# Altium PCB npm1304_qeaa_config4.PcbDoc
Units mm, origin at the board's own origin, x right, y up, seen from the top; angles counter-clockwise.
Board outline 16.8 x 14 mm, 4 copper layers (Top Layer, Mid-Layer 1, Mid-Layer 2, Bottom Layer), stack 1.592 mm thick; 25 components, 32 nets, 81 pads, 59 vias.
Unrouted connection lines stored in the file: 23.
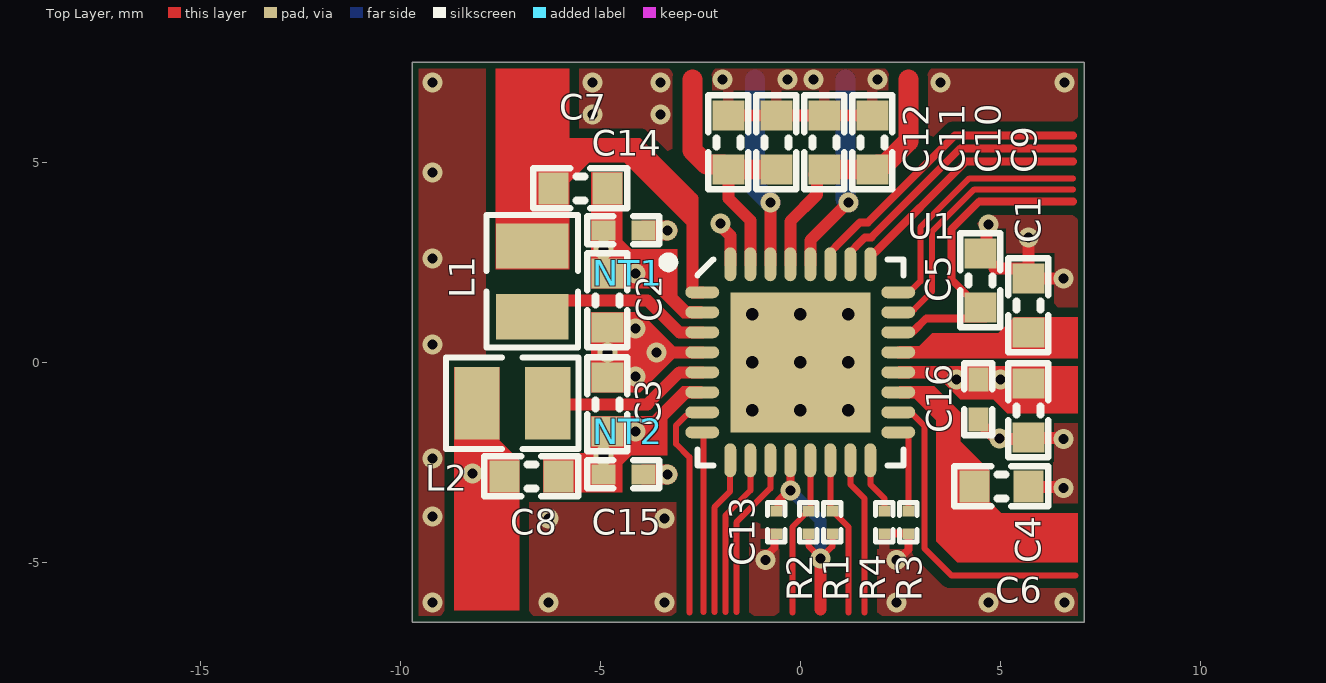
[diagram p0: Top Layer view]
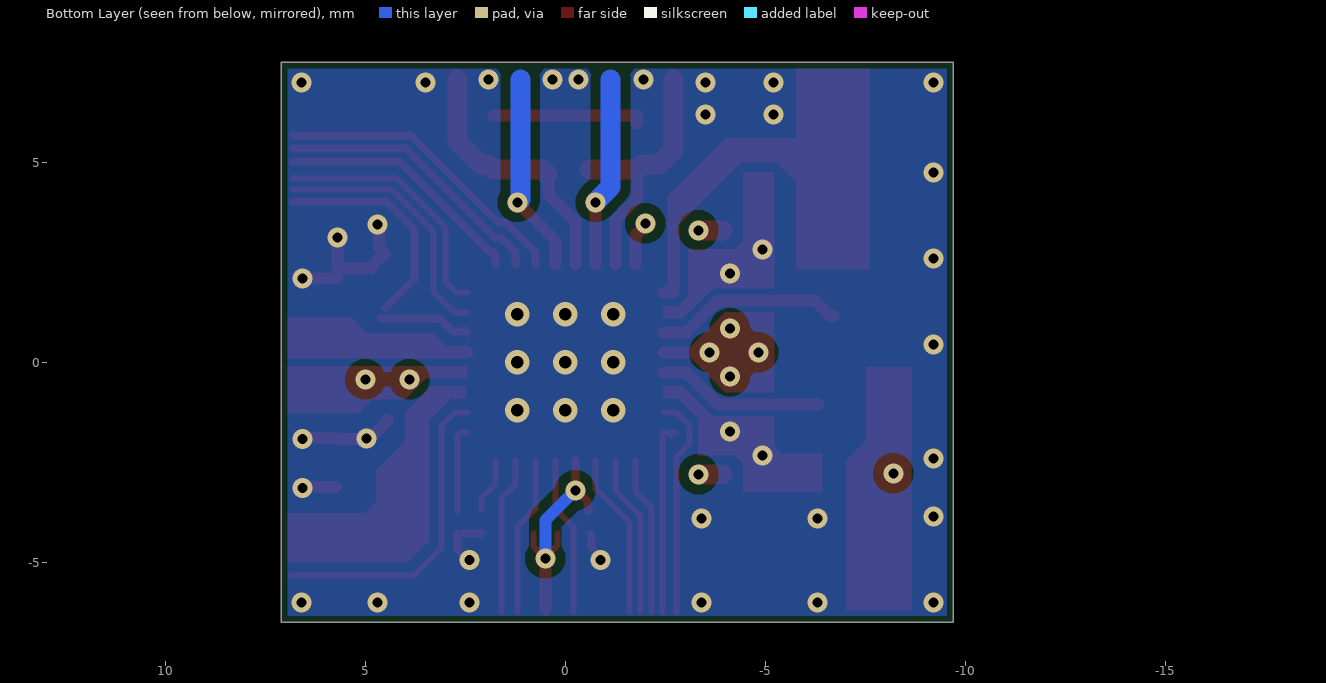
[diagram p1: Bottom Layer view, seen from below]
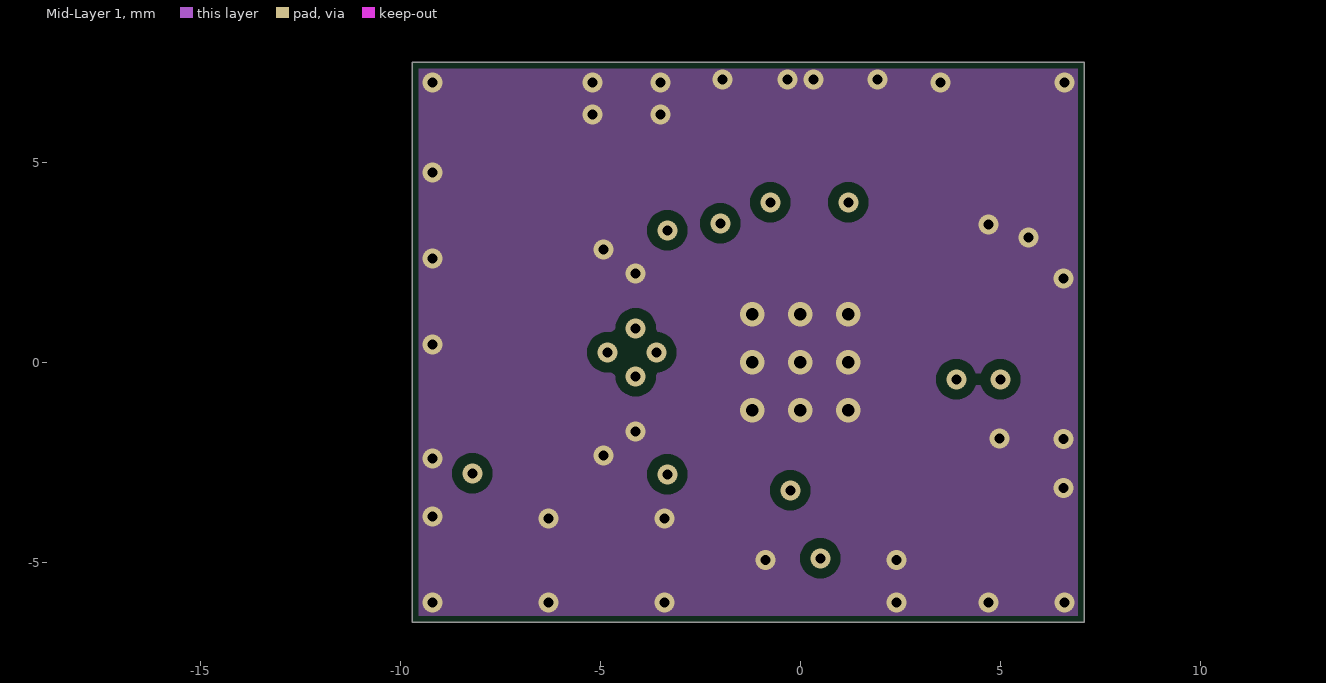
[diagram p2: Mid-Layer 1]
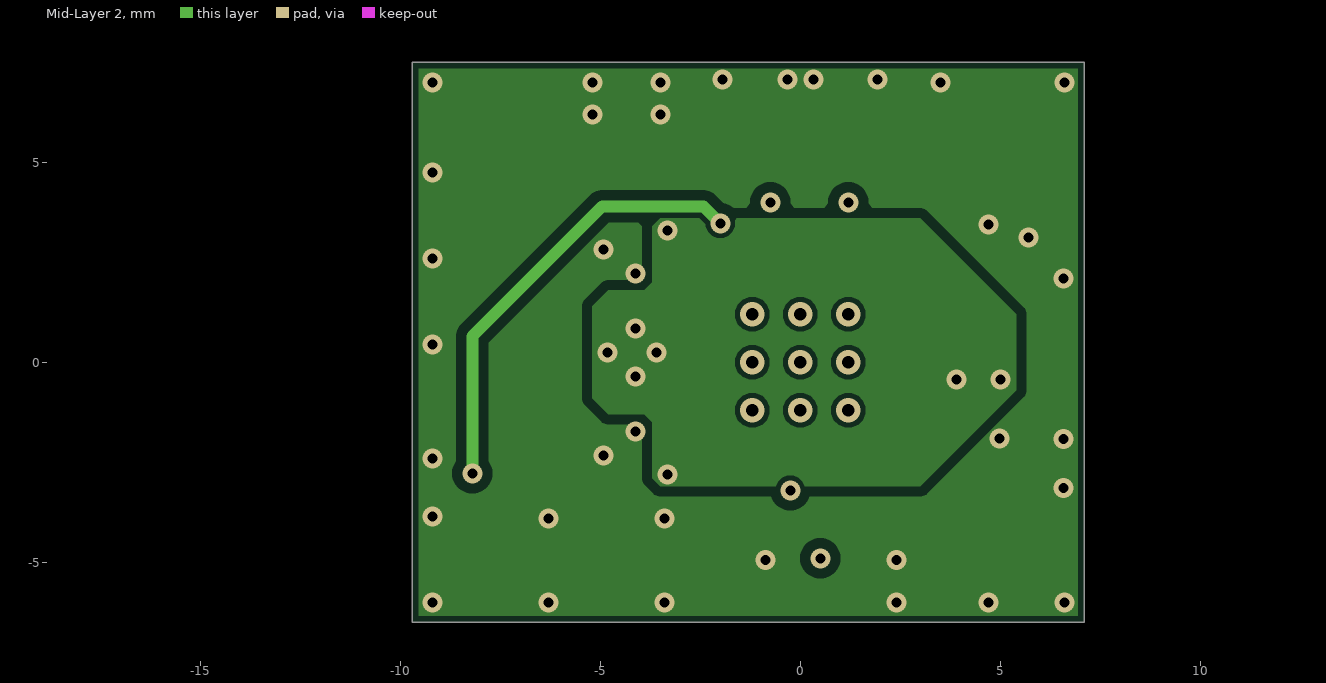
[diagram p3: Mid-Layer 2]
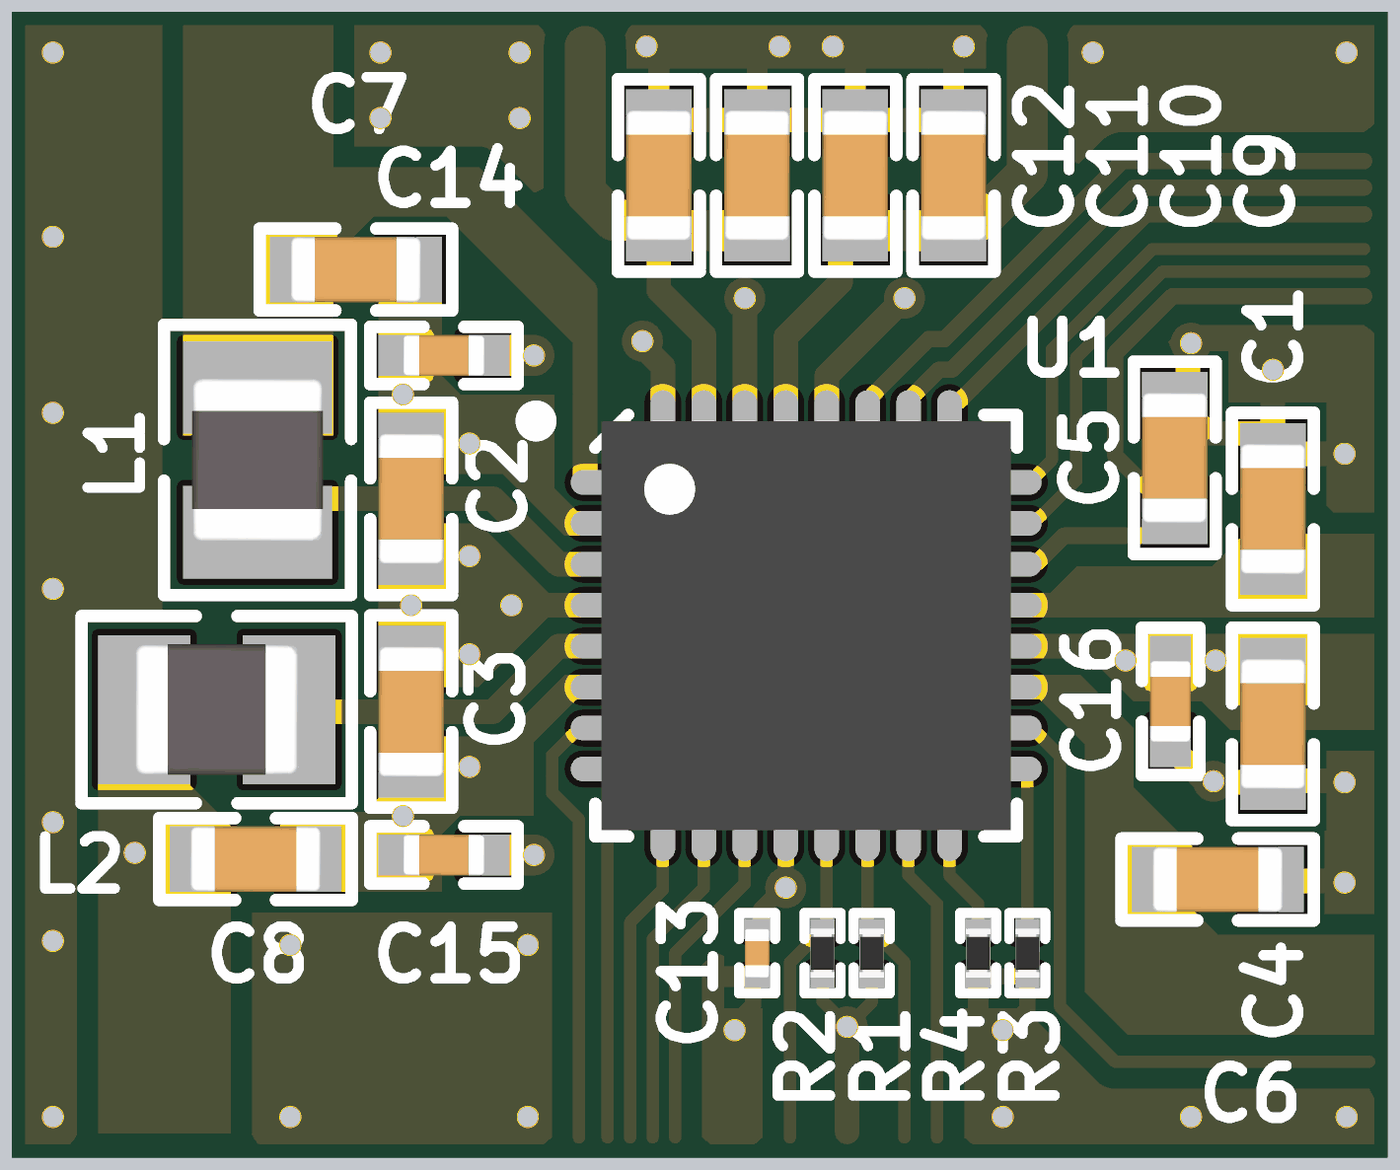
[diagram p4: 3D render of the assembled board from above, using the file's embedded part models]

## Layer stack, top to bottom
Top Solder: solder mask 0.0102, Solder Resist, Dk 3.5
Top Layer: signal copper 0.0356
Dielectric1: prepreg 0.075, FR-4, Dk 4.8
Mid-Layer 1: signal copper 0.0356
Dielectric2: core 1.3, FR-4, Dk 4.8
Mid-Layer 2: signal copper 0.0356
Dielectric 2: prepreg 0.075, FR-4, Dk 4.8
Bottom Layer: signal copper 0.0356
Bottom Solder: solder mask 0.0102, Solder Resist, Dk 3.5

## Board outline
-9.7,-6.5 -9.7,7.5 7.1,7.5 7.1,-6.5

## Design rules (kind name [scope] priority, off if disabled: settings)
BoardOutlineClearance [All] p1: gap=0.15 ignorepadtopadclearanceinfootprint=FALSE
Clearance Clearance_PVSS_Via [InNet('PVSS1') or InNet('PVSS2') vs InNet('GND')] p1: gap=0.125 ignorepadtopadclearanceinfootprint=FALSE except(0.025: SMDPad-Via) // PVSS1 and PVSS2 GND-via clearance
Clearance Polygon_Clearance [(InNamedPolygon('Top_Layer-GND')) or (InNamedPolygon('Bottom_Layer-GND')) or (InNamedPolygon('Mid_Layer_1-GND')) or (InNamedPolygon('Mid_Layer_2-GND'))] p2: gap=0.254 ignorepadtopadclearanceinfootprint=FALSE except(0: Arc-Hole Track-Hole SMDPad-Hole THPad-Hole Via-Hole Fill-Hole Poly-Hole Region-Hole Text-Hole)
Clearance [All] p3: gap=0.125 ignorepadtopadclearanceinfootprint=FALSE
ComponentClearance [All] p1 off: gap=0.254 collisioncheckmode=3 verticalgap=0.254 showdistances=FALSE
DiffPairsRouting [All] p1: maxlimit=0.15 minlimit=0.127 mostfreqgap=0.15 toplayer_mingap=0.15 toplayer_minwidth=0.15 toplayer_maxwidth=0.15 toplayer_prefwidth=0.15 bottomlayer_mingap=0.15 bottomlayer_minwidth=0.15 bottomlayer_maxwidth=0.15 bottomlayer_prefwidth=0.15 impedanceprofiledriven=TRUE impedanceprofileid={DBD80B30-E3CF-4860-A6C7-45E32F93C55D} impedanceprofilevalue=90.000000 maxuncoupledlength=12.7
FabricationTestPointUsage TestPointUsage [All] p1: valid=0 allowmultiple=FALSE
FabricationTestpoint Testpoint [All] p1: side=3 testpointundercomponent=TRUE minsize=1.016 maxsize=2.54 preferedsize=1.524 minholesize=0 maxholesize=1.016 preferedholesize=0.813 testpointgrid=0.025 allowsidetop=TRUE allowsidebottom=TRUE usegrid=TRUE gridtolerance=0
Height [All] p1 off: minheight=0 maxheight=25.4 prefheight=12.7
HoleSize [All] p1: absolutevalues=TRUE maxlimit=5 minlimit=0.1 maxpercent=80.000 minpercent=20.000
MinimumAnnularRing [All] p1 off: minimumring=0.75
PolygonConnect PolygonConnect_GND [InNet('GND')] p1: thpad.connectstyle=Relief thpad.reliefconductorwidth=0.254 thpad.reliefentries=4 thpad.polygonreliefangle="90 Angle" thpad.airgapwidth=0.254 smdpad.connectstyle=Relief smdpad.reliefconductorwidth=0.254 smdpad.reliefentries=4 smdpad.polygonreliefangle="90 Angle" smdpad.airgapwidth=0.254 via.connectstyle=Direct via.reliefconductorwidth=0.254 via.reliefentries=4 via.polygonreliefangle="90 Angle" via.airgapwidth=0.254
PolygonConnect [All] p2: connectstyle=Direct reliefconductorwidth=0.254 reliefentries=4 polygonreliefangle="90 Angle" airgapwidth=0.254
RoutingVias [All] p1: holewidth=0.305 width=0.61 viastyle="Through Hole" minholewidth=0.305 minwidth=0.61 maxholewidth=0.711 maxwidth=1.27 useviatemplates=TRUE viatemplateguid#1={6F225C6A-EE86-4657-A426-C9A0349870D4} viatemplatename#1=v50h25m0mx0
ShortCircuit ShortCircuit_PVSS [InNet('PVSS1') or InNet('PVSS2') vs InNet('GND')] p1: allowed=TRUE
ShortCircuit [All] p2: allowed=FALSE
SilkToSolderMaskClearance SilkscreenOverComponentPads [IsPad] p1: minsilkscreentomaskgap=0.254 clearancetoexposedcopper=TRUE
SolderMaskExpansion SolderMaskExpansion_Vias [IsVia] p1: expansion=0.102 istentingtop=TRUE
SolderMaskExpansion [All] p2: expansion=0.076 istentingtop=FALSE
SupplyNets "Schematic Supply Nets_13" [InNet('PVSS2')] p1: voltage=0.000
SupplyNets "Schematic Supply Nets_12" [InNet('VBUSOUT')] p2: voltage=0.000
SupplyNets "Schematic Supply Nets_11" [InNet('VINLDO2')] p3: voltage=0.000
SupplyNets "Schematic Supply Nets_10" [InNet('VBAT')] p4: voltage=0.000
SupplyNets "Schematic Supply Nets_9" [InNet('VOUTLDO1')] p5: voltage=0.000
SupplyNets "Schematic Supply Nets_8" [InNet('VOUTLDO2')] p6: voltage=0.000
SupplyNets "Schematic Supply Nets_7" [InNet('VDDIO')] p7: voltage=0.000
SupplyNets "Schematic Supply Nets_6" [InNet('GND')] p8: voltage=0.000
SupplyNets "Schematic Supply Nets_5" [InNet('VINLDO1')] p9: voltage=0.000
SupplyNets "Schematic Supply Nets_4" [InNet('VSYS')] p10: voltage=0.000
SupplyNets "Schematic Supply Nets_3" [InNet('VBUSIN')] p11: voltage=0.000
SupplyNets "Schematic Supply Nets_2" [InNet('PVSS1')] p12: voltage=0.000
SupplyNets "Schematic Supply Nets_1" [InNet('VOUT2')] p13: voltage=0.000
SupplyNets "Schematic Supply Nets" [InNet('VOUT1')] p14: voltage=0.000
UnRoutedNet [All] p1: checkbadconnections=TRUE
Width [All] p1: maxlimit=2 minlimit=0.12 preferedwidth=0.3
21 further rules are at their usual default settings.

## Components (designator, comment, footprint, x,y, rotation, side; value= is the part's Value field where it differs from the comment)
C1 "1.0µF" CAPC1608X06L 5.7,1.425 r270 top
C2 "10µF" CAPC1608X06L -4.825,1.55 r270 top
C3 "10µF" CAPC1608X06L -4.825,-1.05 r90 top
C4 "10µF" CAPC1608X06L 5.7,-1.2 r90 top
C5 "1.0µF" CAPC1608X06L 4.5,2.05 r270 top
C6 "2.2µF" CAPC1608X06L 5.025,-3.1 r180 top
C7 "10µF" CAPC1608X06L -5.5,4.35 r180 top
C8 "10µF" CAPC1608X06L -6.725,-2.85 r180 top
C9 "10µF" CAPC1608X06L 1.8,5.5 r270 top
C10 "10µF" CAPC1608X06L 0.6,5.5 r270 top
C11 "10µF" CAPC1608X06L -0.6,5.5 r270 top
C12 "10µF" CAPC1608X06L -1.8,5.5 r270 top
C13 "100nF" CAPC0603X03L_C -0.6,-4 r270 top
C14 "100nF" CAPC1005X04L -4.425,3.3 r180 top
C15 "100nF" CAPC1005X04L -4.425,-2.8 r180 top
C16 "100nF" CAPC1005X04L 4.45,-0.925 r270 top
L1 "2.2µH" INDC2016X10N -6.7,2.025 r270 top
L2 "2.2µH" INDC2016X10N -7.2,-1.025 r0 top
NT1 "Net tie" "2 PIN STARPOINT" -4.317,2.225 r0 top net-tie
NT2 "Net tie" "2 PIN STARPOINT" -4.317,-1.725 r0 top net-tie
R1 "10k" RESC0603X03L_C 0.8,-4 r270 top
R2 "10k" RESC0603X03L_C 0.2,-4 r270 top
R3 "47k" RESC0603X03L_C 2.7,-4 r270 top
R4 "150k" RESC0603X03L_C 2.1,-4 r270 top
U1 "nPM1304-QEAA" Nordic_QFN50P500X500X90-33N 0,0 r0 top locked

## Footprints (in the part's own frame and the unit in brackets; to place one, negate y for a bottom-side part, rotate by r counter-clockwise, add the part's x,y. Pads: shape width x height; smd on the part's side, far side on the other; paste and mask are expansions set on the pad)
"2 PIN STARPOINT" [mil]
  round 6 smd paste-196.85 mask-196.85: 1(8,0) 2(-8,0)
  Top Layer region: -8,-3 8,-3 8,3 -8,3
CAPC0603X03L_C [mm] "Chip Capacitor, 2-Leads, Body 0.6x0.3mm, IPC High Density"
  rect 0.27x0.3 smd mask+0.05: 1(-0.285,0) 2(0.285,0)
  silkscreen extent -0.49,-0.22 0.49,0.22, body extent -0.3,-0.15 0.3,0.15, height 0.3
CAPC1005X04L [mm] "Chip Capacitor, 2-Leads, Body 1.0x0.5mm, IPC High Density"
  rect 0.6x0.5 smd: 1(-0.5,0) 2(0.5,0)
  silkscreen extent -0.9,-0.35 0.9,0.35, body extent -0.5,-0.25 0.5,0.25, height 0.5
CAPC1608X06L [mm] "Chip Capacitor, 2-Leads, Body 1.6x0.8mm, IPC High Density"
  rect 0.75x0.8 smd: 1(-0.675,0) 2(0.675,0)
  silkscreen extent -1.17,-0.5 1.17,0.5, body extent -0.8,-0.4 0.8,0.4, height 0.8
INDC2016X10N [mm] "Chip Inductor, 2-Leads, Body 2.00x1.60mm, IPC Medium Density"
  rect 1.13x1.82 smd: 1(-0.885,0) 2(0.885,0)
  silkscreen extent -1.65,-1.14 1.65,1.14, body extent -1,-0.8 1,0.8, height 1
Nordic_QFN50P500X500X90-33N [mm] "QFN32 5x5x0.85mm, 0.5mm pitch - Medium Density"
  oval 0.85x0.3 smd mask+0.076: 1(-2.45,1.75) 2(-2.45,1.25) 3(-2.45,0.75) 4(-2.45,0.25) 5(-2.45,-0.25) 6(-2.45,-0.75) 7(-2.45,-1.25) 8(-2.45,-1.75) 17(2.45,-1.75) 18(2.45,-1.25) 19(2.45,-0.75) 20(2.45,-0.25) 21(2.45,0.25) 22(2.45,0.75) 23(2.45,1.25) 24(2.45,1.75)
  oval 0.3x0.85 smd mask+0.076: 9(-1.75,-2.45) 10(-1.25,-2.45) 11(-0.75,-2.45) 12(-0.25,-2.45) 13(0.25,-2.45) 14(0.75,-2.45) 15(1.25,-2.45) 16(1.75,-2.45) 25(1.75,2.45) 26(1.25,2.45) 27(0.75,2.45) 28(0.25,2.45) 29(-0.25,2.45) 30(-0.75,2.45) 31(-1.25,2.45) 32(-1.75,2.45)
  rect 3.5x3.5 smd: 33(0,0)
  silkscreen extent -3.42,-2.57 2.57,2.62, body extent -2.5,-2.5 2.5,2.5, height 0.9
RESC0603X03L_C [mm] "Chip Resistor, 2-Leads, Body 0.6x0.3mm, IPC High Density"
  rect 0.27x0.3 smd: 1(-0.285,0) 2(0.285,0)
  silkscreen extent -0.49,-0.22 0.49,0.22, body extent -0.3,-0.15 0.3,0.15, height 0.23

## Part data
C1: library part C0603-1µ0-25V-X5R, "Capacitor, X5R, ±10%, 25V", Manufacturer=N.A., Part number NEMS=100200687
C2 C3 C4 C7 C8 C9 C10 C11 C12: library part C0603-10µ, "Capacitor, X5R, ±20%", Manufacturer=N.A., Part number IPS=00000007785, Part number NEMS=100200275
C5: library part C0603-1µ0-10V-X5R, "Capacitor, Ceramic, 1.0µF 10V X5R 0603,±10%", Manufacturer=N.A., Part number NEMS=100200528
C6: library part C0603-2.2µ-16V-X7R, "Capacitor, Ceramic, X7R, ±10%, 16V", Manufacturer="Taiyo Yuden", Manufacturer Part Number=EMK107BB7225KA-T, Part number IPS=N.A., Part number NEMS=100200439, Supplier Part Number 1=587-5835-2-ND
C13: library part C0201-100n, "Capacitor, X5R, ±10%, 100nF, 16V", Manufacturer=N.A., Part number IPS="00000001248, 00000002505", Part number NEMS=100200078, Part number Norautron=262071862
C14 C15 C16: library part C0402-100n-16V-X7R-C0402C104M4RAC7867, "Capacitor, Ceramic, X7R, ±20%, 16V", Manufacturer=Kemet, Manufacturer Part Number=C0402C104M4RAC7867, Part number IPS=N.A., Part number NEMS=100200504, Supplier Part Number 1=399-C0402C104M4RAC7867CT-ND
L1 L2: library part L0806-2µ2-2500mA-73mOhm-CIGT201610EH2R2MNE, "Inductor, Irms=2.5A, Isat=2.9A, ±20%, DCR=73mΩ", Manufacturer="Samsung Electro-Mechanics America", Manufacturer Part Number=CIGT201610EH2R2MNE, Part number IPS=N.A., Part number NEMS=100300400, Part number Norautron=26521789, Supplier Part Number 1=1276-6901-1-ND
NT1 NT2: library part "2 pin starpoint", "Starpoint", Manufacturer=N.A., Part number NEMS=100500603
R1 R2: library part R0201-10k, "Resistor, ±1%, 0.05W", Manufacturer=N.A., Part number IPS=00000001255, Part number NEMS=100100065, Part number Norautron=26107101
R3: library part R0201-47k, "Resistor, ±1%, 0.05W", Manufacturer=N.A., Part number IPS=00000001423, Part number NEMS=100100076
R4: library part R0201-150k, "Resistor, ±1%, 0.05W", Manufacturer=N.A., Part number IPS=00000001422, Part number NEMS=100100082
U1: "Li-Ion/Li-Polymer USB-C battery charger with high efficiency buck regulators, LDOs or load switches, LED drivers, TWI and VBUSOUT", Manufacturer="Nordic Semiconductor", Part number IPS=N.A., Part number NEMS=102000396

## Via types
v1: diameter 0.5, hole 0.25, Top Layer to Bottom Layer, tented both sides, 50 vias
v2: diameter 0.61, hole 0.305, Top Layer to Bottom Layer, tented both sides, 9 vias

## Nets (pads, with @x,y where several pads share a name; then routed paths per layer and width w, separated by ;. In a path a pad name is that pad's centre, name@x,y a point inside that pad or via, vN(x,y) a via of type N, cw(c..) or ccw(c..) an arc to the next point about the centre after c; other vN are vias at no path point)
CC1: U1.23 | length 6.5
  Top Layer w0.15: U1.23 2.766,1.25 2.841,1.325 2.851,1.325 3.299,1.772 3.299,3.273 4.351,4.325 6.813,4.325
CC2: U1.24 | length 6.3
  Top Layer w0.15: U1.24 2.725,1.75 3,2.025 3,3.375 4.225,4.6 6.813,4.6
GND: C1.1 C4.1 C5.1 C6.1 C9.1 C10.1 C11.1 C12.1 C13.2 C16.2 NT1.1 NT2.1 R3.2 R4.2 U1.33 | length 12.7
  Top Layer w0.2: v1(-0.875,-4.941) -0.875,-4.859 -0.65,-4.634 -0.65,-4.315 C13.2@-0.627,-4.292 ; R4.2 R3.2@2.585,-4.285 ; v1(2.4,-4.941) 2.444,-4.941 2.7,-4.685 R3.2
  Top Layer w0.3: C12.1@-1.8,6 C12.1@-1.775,5.975 ; C12.1 C10.1 C9.1 ; C16.2 4.45,-1.475 v1@4.925,-1.95 ; v1(4.7,3.45) 4.662,3.412 4.662,2.887 C5.1 4.525,2.725 4.85,2.4 4.85,2.35 5.7,2.35 v1(5.7,3.125) ; v1@4.987,-1.912 5.7,-1.912 5.719,-1.894 6.556,-1.894 v1(6.575,-1.912) ; C1.1 v1(6.575,2.1) ; C6.1@5.719,-3.119 v1@6.556,-3.119
  other v1: -9.2,-6 -6.3,-6 -3.4,-6 2.4,-6 4.7,-6 6.6,-6 -6.3,-3.9 -3.4,-3.9 -9.2,-3.85 6.575,-3.137 -9.2,-2.4 -4.925,-2.325 4.975,-1.9 -4.113,-1.725 -9.2,0.45 -4.113,2.225 -9.2,2.6 -4.925,2.825 -9.2,4.75 -5.2,6.2 -3.5,6.2 -9.2,7 -5.2,7 -3.5,7 3.5,7 6.6,7 -1.95,7.075 -0.325,7.075 0.325,7.075 1.925,7.075
  other v2: -1.2,-1.2 0,-1.2 1.2,-1.2 -1.2,0 0,0 1.2,0 -1.2,1.2 0,1.2 1.2,1.2
GPIO0: U1.7 | length 5.6
  Top Layer w0.15: -2.775,-6.25 -2.775,-2.372 -3.103,-2.044 -3.103,-1.578 -2.85,-1.325 -2.841,-1.325 -2.766,-1.25 U1.7
GPIO1: U1.8 | length 4.8
  Top Layer w0.15: U1.8@-2.762,-1.75 -2.581,-1.75 U1.8@-2.65,-1.819 ; U1.8 -2.425,-1.775 -2.425,-6.249
GPIO2: U1.9 | length 4
  Top Layer w0.15: -2.15,-6.249 -2.15,-3.625 -1.753,-3.228 -1.753,-2.453 U1.9
GPIO3: U1.10 | length 4.1
  Top Layer w0.15: -1.875,-6.249 -1.875,-3.83 -1.25,-3.205 U1.10
GPIO4: U1.11 | length 4.2
  Top Layer w0.15: -1.6,-6.249 -1.6,-4 -0.75,-3.15 U1.11
LED0: U1.25 | length 6.3
  Top Layer w0.2: U1.25 1.75,2.698 1.796,2.744 1.869,2.744 4.15,5.025 6.813,5.025
LED1: U1.26 | length 6.9
  Top Layer w0.2: U1.26 1.25,2.752 1.375,2.877 1.375,2.88 1.62,3.125 1.775,3.125 4,5.35 6.813,5.35
LED2: U1.27 | length 7.6
  Top Layer w0.2: U1.27 0.75,2.752 0.875,2.877 0.875,2.88 1.495,3.5 1.69,3.5 3.865,5.675 6.813,5.675
NTC: U1.18 | length 7.9
  Top Layer w0.15: U1.18 2.761,-1.25 3.1,-1.589 3.1,-4.65 3.775,-5.325 6.875,-5.325
PVSS1: C2.1 C7.1 C14.2 NT1.2 U1.2
PVSS2: C3.1 C8.1 C15.2 NT2.2 U1.6
SCL: R1.1 U1.14 | length 4
  Top Layer w0.15: U1.14 0.75,-3.665 R1.1 0.815,-3.715 0.875,-3.775 0.875,-3.79 1.2,-4.115 1.2,-6.25
SDA: R2.1 U1.13 | length 4
  Top Layer w0.15: -0.2,-6.25 -0.2,-4.117 0.125,-3.792 0.125,-3.775 0.22,-3.68 0.25,-3.68 U1.13
SHPHLD: U1.15 | length 3.9
  Top Layer w0.15: U1.15 1.25,-3.05 1.6,-3.4 1.6,-6.25
SW1: L1.2 U1.3 | length 4.8
  Top Layer w0.3: L1.2 -6.65,1.14 -6.24,1.55 -3.825,1.55 -3.025,0.75 -2.725,0.75 U1.3
SW2: L2.2 U1.5 | length 4.2
  Top Layer w0.3: L2.2 -6.315,-1.05 -3.825,-1.05 -3.025,-0.25 -2.725,-0.25 U1.5
VBAT: C6.2 U1.19
VBUSIN: C1.2 U1.21 | length 3.2
  Top Layer w0.3: U1.21 3.487,0.25 4.775,0.25 5.221,0.696 ; C1.2@5.321,0.696 C1.2@5.546,0.696
VBUSOUT: C5.2 U1.22 | length 7.9
  Top Layer w0.2: U1.22 2.469,0.769 2.819,0.769 3.15,1.1 C5.2@4.625,1.1 ; C5.2 4.475,1.375 3.775,2.075 3.775,3.325 4.475,4.025 6.813,4.025
VDDIO: C13.1 R1.2 R2.2 U1.12 | length 6.2
  Top Layer w0.15: R2.2 0.2,-4.586 v1@0.45,-4.836 ; v1@0.5,-4.786 v1(0.5,-4.9) 0.8,-4.6 R1.2
  Top Layer w0.2: C13.1 -0.585,-3.715 -0.55,-3.68 -0.55,-3.467 -0.283,-3.2 v1(-0.25,-3.2) -0.25,-3 U1.12
  Top Layer w0.3: 0.5,-6.182 v1(0.5,-4.9)
  Bottom Layer w0.3: v1(-0.25,-3.2) 0.5,-3.95 v1(0.5,-4.9)
VINLDO1: U1.28 | length 5
  Top Layer w0.3: U1.28 0.25,3.05 v1(1.2,4)
  Bottom Layer w0.5: 1.125,7.075 1.125,4.075 v1(1.2,4)
VINLDO2: U1.30 | length 4.8
  Top Layer w0.3: U1.30 v1(-0.75,4)
  Bottom Layer w0.5: -1.135,7.075 -1.135,4.385 v1(-0.75,4)
VOUT1: C7.2 L1.1 U1.1 | length 3.5
  Top Layer w0.3: -3.352,4.744 -2.7,4.091 -2.7,1.75 U1.1
VOUT2: C8.2 L2.1 U1.32 | length 12.3
  Top Layer w0.3: v1(-2,3.475) -2,3.421 -1.75,3.171 U1.32
  Mid-Layer 2 w0.3: v1(-8.2,-2.775) -8.2,0.65 -4.95,3.9 -2.425,3.9 v1(-2,3.475)
VOUTLDO1: C9.2 C10.2 U1.29 | length 6.7
  Top Layer w0.3: U1.29 -0.25,3.525 0.419,4.194 0.419,4.669 C10.2@0.45,4.7
  Top Layer w0.5: C10.2@0.45,4.7 0.575,4.825 C10.2 C9.2 1.925,4.95 2.125,4.95 2.7,5.525 2.7,7.075
VOUTLDO2: C11.2 C12.2 U1.31 | length 6.7
  Top Layer w0.3: C12.2 -1.8,4.1 -1.25,3.55 U1.31
  Top Layer w0.5: -2.7,7.075 -2.7,5.3 -2.35,4.95 -1.925,4.95 C12.2 C11.2
VSET1: R3.1 U1.17 | length 2.2
  Top Layer w0.15: U1.17 2.631,-1.75 2.7,-1.819 R3.1
VSET2: R4.1 U1.16 | length 1.4
  Top Layer w0.15: U1.16 1.75,-3.05 2.1,-3.4 R4.1@2.1,-3.684
VSYS: C2.2 C3.2 C4.2 C14.1 C15.1 C16.1 U1.4 U1.20 | length 2.3
  Top Layer w0.3: v1(-3.6,0.25) U1.4
  Top Layer w0.5: C15.1 v1(-3.325,-2.8) ; C14.1 v1(-3.325,3.3)
  other v1: 3.9,-0.425 5,-0.425 -4.113,-0.35 -4.825,0.25 -4.113,0.85

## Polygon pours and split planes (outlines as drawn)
GND on Bottom Layer "Bottom_Layer-GND" (solid, remove dead copper, pour order 27): -9.7,-6.5 7.1,-6.5 7.1,7.5 -9.7,7.5
GND on Mid-Layer 1 "Mid_Layer_1-GND" (solid, remove dead copper, pour order 24): -9.7,-6.5 7.1,-6.5 7.1,7.5 -9.7,7.5
VSYS on Mid-Layer 2 "VSYS_PWR" (solid, pour order 25): -3.5,-3.1 -3.7,-2.9 -3.7,-1.5 -3.9,-1.3 -4.8,-1.3 -5.2,-0.9 -5.2,1.4 -4.8,1.8 -3.9,1.8 -3.7,2 -3.7,3.4 -3.5,3.6 3,3.6 5.4,1.2 5.4,-0.7 3,-3.1
GND on Mid-Layer 2 "Mid_Layer_2-GND" (solid, remove dead copper, pour order 26): -9.7,-6.5 7.1,-6.5 7.1,7.5 -9.7,7.5
GND on Top Layer "Top_Layer-GND" (solid, remove dead copper, pour order 21): -9.7,-6.5 7.1,-6.5 7.1,7.5 -9.7,7.5

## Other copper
Top Layer:
  pour cut-out: -6.85,-2.716 -6.85,-3.505 -3.105,-3.505 -3.105,-2.716
  region net VOUT2: -8.65,-2.95 -8.35,-3.25 -8.344,-3.244 -7.025,-3.244 -7.025,-2.45 -7.52,-1.955 -7.52,-0.121 -8.65,-0.121
  region net VSYS: 2.45,-0.4 3.475,-0.4 4,-0.925 4.825,-0.925 5.175,-1.275 6.938,-1.275 6.938,-0.1 2.45,-0.1
  region net VOUT2: -7.025,-2.45 -7.025,-6.2 -8.65,-6.2 -8.65,-2.45
  region net VOUT1: -7.61,3.938 -7.61,7.338 -5.775,7.338 -5.775,3.938
  region net PVSS2: -5.225,-2.1 -5.4,-2.275 -6.425,-2.275 -6.425,-3.25 -4.45,-3.25 -4.45,-2.55 -4.225,-2.325 -3.325,-2.325 -3.325,-1.425 -2.8,-0.9 -2.45,-0.9 -2.45,-0.6 -2.95,-0.6 -3.7,-1.35 -5.225,-1.35
  region net PVSS1: -5.225,1.85 -3.7,1.85 -2.95,1.1 -2.45,1.1 -2.45,1.4 -2.8,1.4 -3.075,1.675 -3.075,2.825 -4.225,2.825 -4.45,3.05 -4.45,4.75 -5.225,4.75 -5.225,2.825
  region net VOUT1: -5.275,5 -4.4,5 -2.775,3.375 -2.65,3.375 -2.65,4.25 -4,5.6 -6.85,5.6 -7.61,4.84 -7.61,2.325 -5.775,2.325 -5.775,4.5
  region net VSYS: -3.15,0.4 -4,1.25 -5.225,1.25 -5.225,-0.75 -4,-0.75 -3.15,0.1
  pour cut-out: -7.864,2.325 -7.864,-0.115 -5.775,-0.115 -5.775,2.325
  region net VBAT: 2.475,-0.9 2.85,-0.9 3.4,-1.45 3.4,-4.475 3.925,-5 6.938,-5 6.938,-3.775 5.025,-3.775 4.725,-3.475 4.725,-2.7 4,-1.975 4,-1.25 3.35,-0.6 2.475,-0.6
  region net VBUSIN: 2.475,0.4 2.975,0.4 3.3,0.725 4.95,0.725 5.35,1.125 6.938,1.125 6.938,0.1 2.475,0.1
  pour cut-out: -1.85,1.85 1.85,1.85 1.85,-1.85 -1.85,-1.85
  pour cut-out: -17.9,1.7 -17.9,-3.2
  pour cut-out: 7.375,0.45 7.375,-0.41
Mid-Layer 1:
  pour cut-out: 11.025,5.525 12.025,5.525

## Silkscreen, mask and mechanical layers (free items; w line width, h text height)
Board Outline:
  the board outline again, w0.2

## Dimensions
7.1,7.5 to 7.1,-6.5 on Dimension
-9.7,-6.5 to 7.1,-6.5 on Dimension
